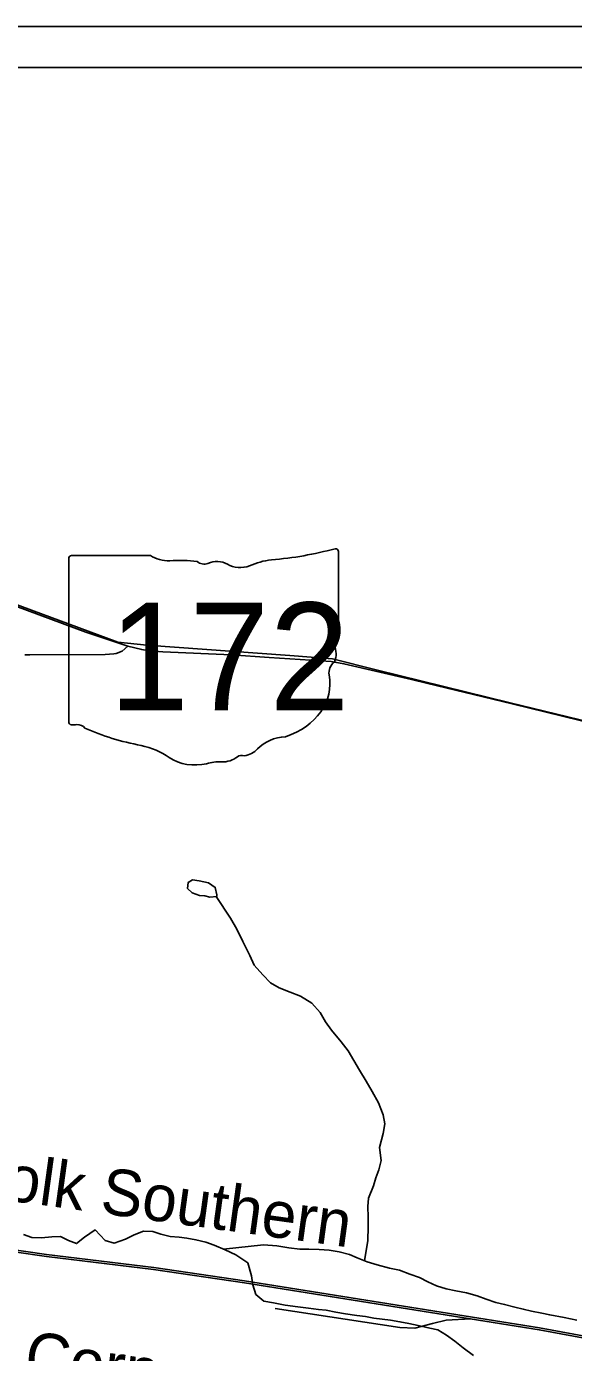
# Model space of a CAD drawing. Extents: x 25.6 to 80.6, y 0.2 to 24.5.
# Drawn here: x 44.756 to 46.093, y 14.588 to 17.83 of the extents above; entities that cross this region are included whole.
import ezdxf

# ---------------------------------------------------------------- set-up
doc = ezdxf.new("R2010")
doc.units = 0
for name, color, linetype in [('GM_X_County_Road', 7, 'Continuous'), ('GM_X_Minor_Lake', 7, 'Continuous'), ('GM_X_Minor_River', 7, 'Continuous'), ('GM_X_Rail_Line', 7, 'Continuous'), ('GM_X_Rail_Line_Text', 7, 'Continuous'), ('GM_X_State_Route', 7, 'Continuous'), ('GM_X_State_Shield', 7, 'Continuous'), ('SH_Data', 7, 'Continuous'), ('SH_Text', 7, 'Continuous')]:
    doc.layers.add(name, color=color, linetype=linetype)

msp = doc.modelspace()

# ---------------------------------------------------------------- linework, layer by layer
at = {"layer": 'GM_X_County_Road'}
for points in [[(44.9691, 16.2966), (44.9748, 16.2971), (44.9899, 16.303), (45.0032, 16.3151)], [(44.7518, 16.2938), (44.7637, 16.2941), (44.9482, 16.2948), (44.9691, 16.2966)]]:
    msp.add_lwpolyline(points, dxfattribs=at)
at = {"layer": 'GM_X_Minor_Lake'}
for points in [[(45.2207, 15.7072), (45.2174, 15.7254), (45.2006, 15.7366), (45.1778, 15.7416), (45.1618, 15.7436), (45.1513, 15.7374), (45.1492, 15.723), (45.1607, 15.7117)], [(45.1607, 15.7117), (45.1788, 15.7058), (45.1916, 15.7043), (45.2043, 15.7016), (45.2211, 15.7032), (45.2207, 15.7072)]]:
    msp.add_lwpolyline(points, dxfattribs=at)
at = {"layer": 'GM_X_Minor_River'}
for points in [[(45.5822, 14.8123), (45.5903, 14.8622), (45.5914, 14.8956), (45.591, 14.9192), (45.5899, 14.945), (45.5919, 14.9655), (45.6044, 14.9953), (45.6102, 15.0152), (45.6175, 15.0343), (45.6225, 15.0579), (45.6191, 15.089), (45.6277, 15.1233), (45.6319, 15.1469), (45.6279, 15.1689), (45.6161, 15.1984), (45.6005, 15.2263), (45.5858, 15.2519), (45.5695, 15.2783), (45.5562, 15.3024), (45.5423, 15.3258), (45.5253, 15.3476), (45.5014, 15.3761), (45.4867, 15.3964), (45.4735, 15.419), (45.4534, 15.4423), (45.4259, 15.4594), (45.4, 15.4689), (45.3733, 15.4799), (45.3526, 15.4918), (45.3334, 15.5113), (45.3126, 15.5353), (45.3016, 15.5587), (45.2845, 15.5934), (45.2696, 15.6228), (45.2541, 15.65), (45.2196, 15.7031)], [(44.7487, 14.8762), (44.7685, 14.8696), (44.7921, 14.8684), (44.8178, 14.8711), (44.8391, 14.8714), (44.8582, 14.8618), (44.878, 14.8544), (44.8975, 14.8699), (44.9238, 14.8877), (44.9477, 14.8622), (44.9698, 14.855), (44.9977, 14.8652), (45.0188, 14.8754), (45.0415, 14.8848), (45.0642, 14.8836), (45.0841, 14.8771), (45.1069, 14.8721), (45.1289, 14.8701), (45.1479, 14.8673), (45.17, 14.8639), (45.1943, 14.8581), (45.2149, 14.8501), (45.2416, 14.839), (45.2676, 14.8272), (45.2967, 14.8071), (45.3055, 14.7753), (45.3095, 14.7534), (45.3167, 14.7299), (45.3359, 14.7135), (45.3595, 14.7092), (45.3884, 14.7036), (45.4195, 14.6994), (45.4454, 14.6968), (45.4697, 14.6933), (45.4887, 14.6913), (45.5123, 14.6863), (45.5358, 14.6828), (45.5632, 14.6787), (45.5845, 14.6759), (45.605, 14.6724), (45.6255, 14.6697), (45.6453, 14.6669), (45.6689, 14.6634), (45.6902, 14.6592), (45.713, 14.6542), (45.7419, 14.6477), (45.7617, 14.6435), (45.7824, 14.6301), (45.803, 14.6159), (45.823, 14.5995), (45.8483, 14.5809)], [(45.2371, 14.8409), (45.3355, 14.8517), (45.3674, 14.8492), (45.3971, 14.8443), (45.4237, 14.8408), (45.4457, 14.8404), (45.4715, 14.84), (45.4958, 14.838), (45.5201, 14.8346), (45.5452, 14.8273), (45.5643, 14.8193), (45.5887, 14.8097), (45.6131, 14.8025), (45.6436, 14.7945), (45.6679, 14.7896), (45.6931, 14.78), (45.7167, 14.7712), (45.7366, 14.7609), (45.758, 14.7513), (45.7816, 14.744), (45.8052, 14.7391), (45.8318, 14.7341), (45.8577, 14.7269), (45.8798, 14.7181), (45.9034, 14.71), (45.9247, 14.7058), (45.9499, 14.6985), (45.9704, 14.6943), (45.9902, 14.6892), (46.0153, 14.6843), (46.0351, 14.68), (46.0701, 14.6736), (46.1013, 14.6672)]]:
    msp.add_lwpolyline(points, dxfattribs=at)
at = {"layer": 'GM_X_Rail_Line'}
for points in [[(47.8128, 15.8191), (47.6057, 15.8302), (47.3402, 15.8521), (47.1631, 15.8871), (46.9912, 15.9223), (46.7273, 15.9853), (45.9383, 16.1769), (45.6136, 16.2567), (45.5036, 16.2842), (45.3992, 16.2924), (45.0499, 16.3176), (44.9789, 16.3252), (44.6728, 16.4383), (44.4128, 16.5397)], [(44.4128, 14.8771), (44.4231, 14.8756), (44.5249, 14.8648), (44.6048, 14.8557), (44.6465, 14.8507), (44.805, 14.8274), (45.0669, 14.7959), (45.2891, 14.7633), (46.0102, 14.6483), (46.3148, 14.5918), (46.4227, 14.5651), (46.528, 14.5372), (46.6857, 14.4857), (46.9234, 14.4078), (47.0403, 14.372), (47.1373, 14.3511), (47.2255, 14.3378), (47.2936, 14.3374), (47.3809, 14.3425), (47.4529, 14.3573), (47.553, 14.386), (47.7232, 14.4468), (47.8128, 14.4801)], [(44.4128, 14.8724), (44.4226, 14.871), (44.5243, 14.8601), (44.6043, 14.851), (44.6459, 14.846), (44.8044, 14.8227), (45.0663, 14.7912), (45.2884, 14.7586), (46.0094, 14.6437), (46.3138, 14.5872), (46.4216, 14.5606), (46.5266, 14.5327), (46.6843, 14.4812), (46.9219, 14.4033), (47.0391, 14.3674), (47.1365, 14.3464), (47.2252, 14.3331), (47.2937, 14.3327), (47.3816, 14.3378), (47.454, 14.3527), (47.5545, 14.3816), (47.7248, 14.4424), (47.8128, 14.4751)], [(45.3633, 14.6957), (45.6684, 14.649), (45.705, 14.6479), (45.7483, 14.6588), (45.7819, 14.6674), (45.8411, 14.6705)]]:
    msp.add_lwpolyline(points, dxfattribs=at)
at = {"layer": 'GM_X_State_Route'}
for points in [[(44.4128, 16.5349), (44.7012, 16.4233), (44.9007, 16.3494), (45.0032, 16.3151), (45.0376, 16.3068), (45.0416, 16.3062)], [(45.0416, 16.3062), (45.0578, 16.3038), (45.0891, 16.3016), (45.2571, 16.2936), (45.3492, 16.2878), (45.5006, 16.2775), (45.5317, 16.2723), (45.6971, 16.2334)], [(45.6971, 16.2334), (45.734, 16.2247), (45.9432, 16.1743), (46.1495, 16.1236), (46.3002, 16.0879), (46.4014, 16.0619)]]:
    msp.add_lwpolyline(points, dxfattribs=at)
at = {"layer": 'GM_X_State_Shield'}
for p, q in [((45.0588, 16.5369), (44.8657, 16.5369)), ((45.5184, 16.3374), (45.5184, 16.5468)), ((44.8593, 16.53), (44.8593, 16.1297)), ((45.5184, 16.3375), (45.5184, 16.3374))]:
    msp.add_line(p, q, dxfattribs=at)
for centre, major_axis, start_param, end_param in [((44.8668, 16.5308), (0.00764, 0), 1.712693, 3.28349), ((45.1048, 16.5833), (0.0741, 0), 4.042523, 4.731795), ((45.2836, 17.0825), (0.699, 0), 4.814394, 5.042369), ((45.5111, 16.5476), (0.00734, 0), 6.141152, 7.989035), ((45.1293, 16.3122), (0.2659, 0), 1.404758, 1.657858), ((45.1897, 16.5329), (0.0214, 0), 3.836095, 5.185415), ((45.2211, 16.4866), (0.0444, 0), 0.950623, 2.079405), ((45.2784, 16.5501), (0.0534, 0), 4.081561, 5.145723), ((45.3728, 16.4146), (0.1406, 0), 1.699011, 2.107814), ((45.5167, 16.322), (0.0114, 0), 1.883978, 3.671073), ((45.4445, 16.2956), (0.0682, 0), 5.934695, 6.695948), ((45.5106, 16.3366), (0.00785, 0), 5.05454, 6.418171), ((45.5447, 16.2498), (0.0496, 0), 2.387724, 3.262537), ((45.3228, 16.2231), (0.1748, 0), 5.101752, 6.440018), ((44.8669, 16.1289), (0.0077, 0), 3.00124, 4.508301), ((44.868, 16.1698), (0.0588, 0), 4.665946, 4.897461), ((44.8801, 16.1066), (0.0212, 0), 0.519207, 1.627899), ((45.1477, 16.4662), (0.5048, 0), 4.195997, 4.488961), ((45.3965, 16.0174), (0.0958, 0), 1.647645, 2.488434), ((44.9972, 15.9499), (0.1579, 0), 0.823519, 1.323587), ((45.2816, 16.0359), (0.015, 0), 1.147584, 2.315152), ((45.2752, 16.0909), (0.0565, 0), 4.937069, 5.64225), ((45.168, 16.1047), (0.1002, 0), 4.026481, 4.996735), ((45.226, 15.9663), (0.0824, 0), 1.495662, 1.94098), ((45.2333, 16.0747), (0.0534, 0), 4.691044, 5.507374)]:
    msp.add_ellipse(centre, major_axis=major_axis, ratio=0.8, start_param=start_param, end_param=end_param, dxfattribs=at)
at = {"layer": 'SH_Data'}
msp.add_line((44.5128, 17.8303), (47.9128, 17.8303), dxfattribs=at)
at = {"layer": 'SH_Text'}
msp.add_lwpolyline([(44.4128, 14.3303), (47.8128, 14.3303), (47.8128, 17.7303), (44.4128, 17.7303)], close=True, dxfattribs=at)

# ---------------------------------------------------------------- texts
at = {"layer": 'GM_X_Rail_Line_Text'}
for s, rotation, p in [('Norfolk Southern', 352.1349, (44.4163, 15.0006)), ('Corporation', 351.8832, (44.7466, 14.5293))]:
    msp.add_text(s, height=0.113258, rotation=rotation, dxfattribs=at).set_placement(p)
at = {"layer": 'GM_X_State_Shield'}
msp.add_text('172', height=0.26367, dxfattribs=at).set_placement((44.9572, 16.158))

doc.saveas('drawing.dxf')
